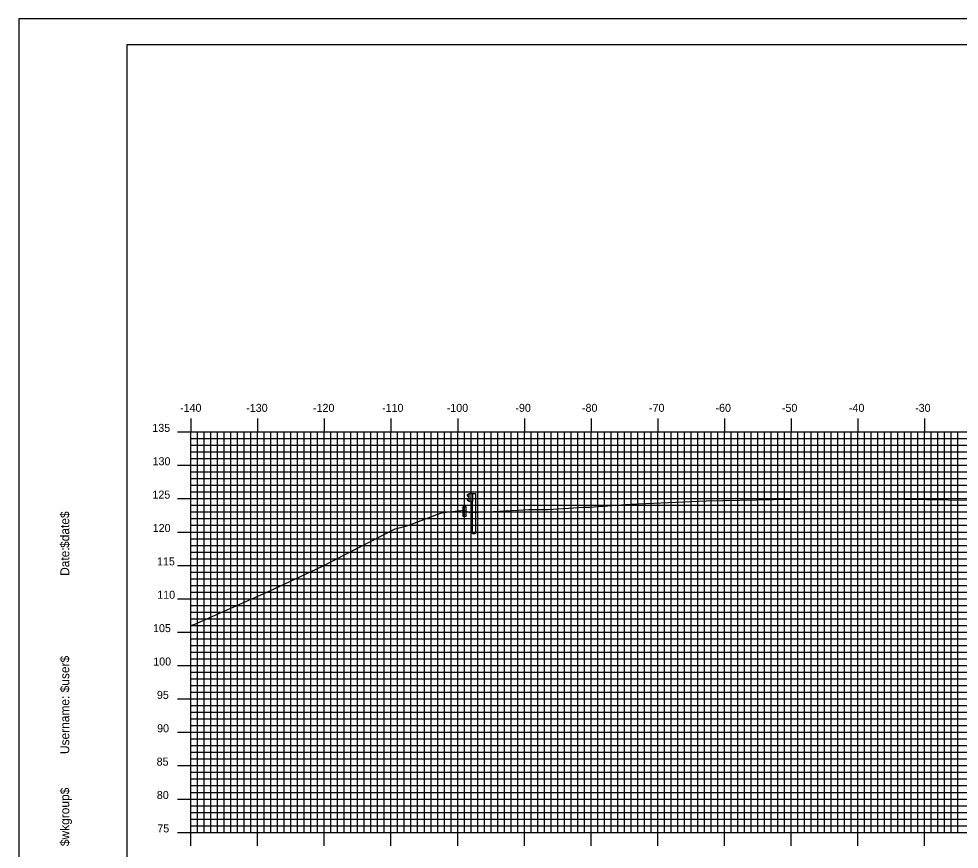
# Model space of a CAD drawing. Extents: x 857265 to 857608, y 364366 to 364586.
# Drawn here: x 857264.5 to 857405.5, y 364461.3 to 364585.7 of the extents above; entities that cross this region are included whole.
import ezdxf

# ---------------------------------------------------------------- set-up
doc = ezdxf.new("R2010")
doc.units = 0
for name, color, linetype in [('BORDER', 7, 'Continuous'), ('H_V ANNOTATION', 7, 'Continuous'), ('M_Roadway_Centerline', 7, 'Continuous'), ('MAJOR', 7, 'Continuous'), ('MINOR', 7, 'Continuous'), ('PLOT BOUNDARY', 7, 'Continuous'), ('S_Curb_Type_1', 7, 'Continuous'), ('S_Guardrail_Beam', 7, 'Continuous'), ('S_Roadway_Centerline', 7, 'Continuous')]:
    doc.layers.add(name, color=color, linetype=linetype)

msp = doc.modelspace()

# ---------------------------------------------------------------- linework, layer by layer
at = {"layer": 'BORDER'}
msp.add_lwpolyline([(857280.74, 364371.79), (857600.74, 364371.79), (857600.74, 364581.79), (857280.74, 364581.79)], close=True, dxfattribs=at)
at = {"layer": 'MAJOR'}
for p, q in [((857290.34, 364525.79), (857290.34, 364523.79)), ((857300.34, 364525.79), (857300.34, 364523.79)), ((857310.34, 364525.79), (857310.34, 364523.79)), ((857320.34, 364525.79), (857320.34, 364523.79)), ((857330.34, 364525.79), (857330.34, 364523.79)), ((857340.34, 364525.79), (857340.34, 364523.79)), ((857350.34, 364525.79), (857350.34, 364523.79)), ((857360.34, 364525.79), (857360.34, 364523.79)), ((857370.34, 364525.79), (857370.34, 364523.79)), ((857380.34, 364525.79), (857380.34, 364523.79)), ((857390.34, 364525.79), (857390.34, 364523.79)), ((857400.34, 364525.79), (857400.34, 364523.79)), ((857288.33, 364523.79), (857290.34, 364523.79)), ((857290.34, 364523.79), (857570.34, 364523.79)), ((857290.34, 364463.79), (857290.34, 364523.79)), ((857290.34, 364463.79), (857290.34, 364523.79)), ((857290.34, 364523.79), (857570.34, 364523.79)), ((857300.34, 364463.79), (857300.34, 364523.79)), ((857310.34, 364463.79), (857310.34, 364523.79)), ((857320.34, 364463.79), (857320.34, 364523.79)), ((857330.34, 364463.79), (857330.34, 364523.79)), ((857340.34, 364463.79), (857340.34, 364523.79)), ((857350.34, 364463.79), (857350.34, 364523.79)), ((857360.34, 364463.79), (857360.34, 364523.79)), ((857370.34, 364463.79), (857370.34, 364523.79)), ((857380.34, 364463.79), (857380.34, 364523.79)), ((857390.34, 364463.79), (857390.34, 364523.79)), ((857400.34, 364463.79), (857400.34, 364523.79)), ((857288.33, 364518.79), (857290.34, 364518.79)), ((857290.34, 364518.79), (857570.34, 364518.79)), ((857288.33, 364513.79), (857290.34, 364513.79)), ((857290.34, 364513.79), (857570.34, 364513.79)), ((857288.33, 364508.79), (857290.34, 364508.79)), ((857290.34, 364508.79), (857570.34, 364508.79)), ((857288.33, 364503.79), (857290.34, 364503.79)), ((857290.34, 364503.79), (857570.34, 364503.79)), ((857288.33, 364498.79), (857290.34, 364498.79)), ((857290.34, 364498.79), (857570.34, 364498.79)), ((857288.33, 364493.79), (857290.34, 364493.79)), ((857290.34, 364493.79), (857570.34, 364493.79)), ((857288.33, 364488.79), (857290.34, 364488.79)), ((857290.34, 364488.79), (857570.34, 364488.79)), ((857288.33, 364483.79), (857290.34, 364483.79)), ((857290.34, 364483.79), (857570.34, 364483.79)), ((857288.33, 364478.79), (857290.34, 364478.79)), ((857290.34, 364478.79), (857570.34, 364478.79)), ((857288.33, 364473.79), (857290.34, 364473.79)), ((857290.34, 364473.79), (857570.34, 364473.79)), ((857288.33, 364468.79), (857290.34, 364468.79)), ((857290.34, 364468.79), (857570.34, 364468.79)), ((857288.33, 364463.79), (857290.34, 364463.79)), ((857290.34, 364463.79), (857570.34, 364463.79)), ((857290.34, 364463.79), (857570.34, 364463.79)), ((857290.34, 364461.78), (857290.34, 364463.79)), ((857300.34, 364461.78), (857300.34, 364463.79)), ((857310.34, 364461.78), (857310.34, 364463.79)), ((857320.34, 364461.78), (857320.34, 364463.79)), ((857330.34, 364461.78), (857330.34, 364463.79)), ((857340.34, 364461.78), (857340.34, 364463.79)), ((857350.34, 364461.78), (857350.34, 364463.79)), ((857360.34, 364461.78), (857360.34, 364463.79)), ((857370.34, 364461.78), (857370.34, 364463.79)), ((857380.34, 364461.78), (857380.34, 364463.79)), ((857390.34, 364461.78), (857390.34, 364463.79)), ((857400.34, 364461.78), (857400.34, 364463.79))]:
    msp.add_line(p, q, dxfattribs=at)
at = {"layer": 'MINOR'}
for p, q in [((857291.34, 364463.79), (857291.34, 364523.79)), ((857292.34, 364463.79), (857292.34, 364523.79)), ((857293.34, 364463.79), (857293.34, 364523.79)), ((857294.34, 364463.79), (857294.34, 364523.79)), ((857295.34, 364463.79), (857295.34, 364523.79)), ((857296.34, 364463.79), (857296.34, 364523.79)), ((857297.34, 364463.79), (857297.34, 364523.79)), ((857298.34, 364463.79), (857298.34, 364523.79)), ((857299.34, 364463.79), (857299.34, 364523.79)), ((857301.34, 364463.79), (857301.34, 364523.79)), ((857302.34, 364463.79), (857302.34, 364523.79)), ((857303.34, 364463.79), (857303.34, 364523.79)), ((857304.34, 364463.79), (857304.34, 364523.79)), ((857305.34, 364463.79), (857305.34, 364523.79)), ((857306.34, 364463.79), (857306.34, 364523.79)), ((857307.34, 364463.79), (857307.34, 364523.79)), ((857308.34, 364463.79), (857308.34, 364523.79)), ((857309.34, 364463.79), (857309.34, 364523.79)), ((857311.34, 364463.79), (857311.34, 364523.79)), ((857312.34, 364463.79), (857312.34, 364523.79)), ((857313.34, 364463.79), (857313.34, 364523.79)), ((857314.34, 364463.79), (857314.34, 364523.79)), ((857315.34, 364463.79), (857315.34, 364523.79)), ((857316.34, 364463.79), (857316.34, 364523.79)), ((857317.34, 364463.79), (857317.34, 364523.79)), ((857318.34, 364463.79), (857318.34, 364523.79)), ((857319.34, 364463.79), (857319.34, 364523.79)), ((857321.34, 364463.79), (857321.34, 364523.79)), ((857322.34, 364463.79), (857322.34, 364523.79)), ((857323.34, 364463.79), (857323.34, 364523.79)), ((857324.34, 364463.79), (857324.34, 364523.79)), ((857325.34, 364463.79), (857325.34, 364523.79)), ((857326.34, 364463.79), (857326.34, 364523.79)), ((857327.34, 364463.79), (857327.34, 364523.79)), ((857328.34, 364463.79), (857328.34, 364523.79)), ((857329.34, 364463.79), (857329.34, 364523.79)), ((857331.34, 364463.79), (857331.34, 364523.79)), ((857332.34, 364463.79), (857332.34, 364523.79)), ((857333.34, 364463.79), (857333.34, 364523.79)), ((857334.34, 364463.79), (857334.34, 364523.79)), ((857335.34, 364463.79), (857335.34, 364523.79)), ((857336.34, 364463.79), (857336.34, 364523.79)), ((857337.34, 364463.79), (857337.34, 364523.79)), ((857338.34, 364463.79), (857338.34, 364523.79)), ((857339.34, 364463.79), (857339.34, 364523.79)), ((857341.34, 364463.79), (857341.34, 364523.79)), ((857342.34, 364463.79), (857342.34, 364523.79)), ((857343.34, 364463.79), (857343.34, 364523.79)), ((857344.34, 364463.79), (857344.34, 364523.79)), ((857345.34, 364463.79), (857345.34, 364523.79)), ((857346.34, 364463.79), (857346.34, 364523.79)), ((857347.34, 364463.79), (857347.34, 364523.79)), ((857348.34, 364463.79), (857348.34, 364523.79)), ((857349.34, 364463.79), (857349.34, 364523.79)), ((857351.34, 364463.79), (857351.34, 364523.79)), ((857352.34, 364463.79), (857352.34, 364523.79)), ((857353.34, 364463.79), (857353.34, 364523.79)), ((857354.34, 364463.79), (857354.34, 364523.79)), ((857355.34, 364463.79), (857355.34, 364523.79)), ((857356.34, 364463.79), (857356.34, 364523.79)), ((857357.34, 364463.79), (857357.34, 364523.79)), ((857358.34, 364463.79), (857358.34, 364523.79)), ((857359.34, 364463.79), (857359.34, 364523.79)), ((857361.34, 364463.79), (857361.34, 364523.79)), ((857362.34, 364463.79), (857362.34, 364523.79)), ((857363.34, 364463.79), (857363.34, 364523.79)), ((857364.34, 364463.79), (857364.34, 364523.79)), ((857365.34, 364463.79), (857365.34, 364523.79)), ((857366.34, 364463.79), (857366.34, 364523.79)), ((857367.34, 364463.79), (857367.34, 364523.79)), ((857368.34, 364463.79), (857368.34, 364523.79)), ((857369.34, 364463.79), (857369.34, 364523.79)), ((857371.34, 364463.79), (857371.34, 364523.79)), ((857372.34, 364463.79), (857372.34, 364523.79)), ((857373.34, 364463.79), (857373.34, 364523.79)), ((857374.34, 364463.79), (857374.34, 364523.79)), ((857375.34, 364463.79), (857375.34, 364523.79)), ((857376.34, 364463.79), (857376.34, 364523.79)), ((857377.34, 364463.79), (857377.34, 364523.79)), ((857378.34, 364463.79), (857378.34, 364523.79)), ((857379.34, 364463.79), (857379.34, 364523.79)), ((857381.34, 364463.79), (857381.34, 364523.79)), ((857382.34, 364463.79), (857382.34, 364523.79)), ((857383.34, 364463.79), (857383.34, 364523.79)), ((857384.34, 364463.79), (857384.34, 364523.79)), ((857385.34, 364463.79), (857385.34, 364523.79)), ((857386.34, 364463.79), (857386.34, 364523.79)), ((857387.34, 364463.79), (857387.34, 364523.79)), ((857388.34, 364463.79), (857388.34, 364523.79)), ((857389.34, 364463.79), (857389.34, 364523.79)), ((857391.34, 364463.79), (857391.34, 364523.79)), ((857392.34, 364463.79), (857392.34, 364523.79)), ((857393.34, 364463.79), (857393.34, 364523.79)), ((857394.34, 364463.79), (857394.34, 364523.79)), ((857395.34, 364463.79), (857395.34, 364523.79)), ((857396.34, 364463.79), (857396.34, 364523.79)), ((857397.34, 364463.79), (857397.34, 364523.79)), ((857398.34, 364463.79), (857398.34, 364523.79)), ((857399.34, 364463.79), (857399.34, 364523.79)), ((857401.34, 364463.79), (857401.34, 364523.79)), ((857402.34, 364463.79), (857402.34, 364523.79)), ((857403.34, 364463.79), (857403.34, 364523.79)), ((857404.34, 364463.79), (857404.34, 364523.79)), ((857405.34, 364463.79), (857405.34, 364523.79)), ((857290.34, 364522.79), (857570.34, 364522.79)), ((857290.34, 364522.79), (857292.34, 364522.79)), ((857290.34, 364521.79), (857570.34, 364521.79)), ((857290.34, 364521.79), (857292.34, 364521.79)), ((857290.34, 364520.79), (857570.34, 364520.79)), ((857290.34, 364520.79), (857292.34, 364520.79)), ((857290.34, 364519.79), (857570.34, 364519.79)), ((857290.34, 364519.79), (857292.34, 364519.79)), ((857290.34, 364517.79), (857570.34, 364517.79)), ((857290.34, 364517.79), (857292.34, 364517.79)), ((857290.34, 364516.79), (857570.34, 364516.79)), ((857290.34, 364516.79), (857292.34, 364516.79)), ((857290.34, 364515.79), (857570.34, 364515.79)), ((857290.34, 364515.79), (857292.34, 364515.79)), ((857290.34, 364514.79), (857570.34, 364514.79)), ((857290.34, 364514.79), (857292.34, 364514.79)), ((857290.34, 364512.79), (857570.34, 364512.79)), ((857290.34, 364512.79), (857292.34, 364512.79)), ((857290.34, 364511.79), (857570.34, 364511.79)), ((857290.34, 364511.79), (857292.34, 364511.79)), ((857290.34, 364510.79), (857570.34, 364510.79)), ((857290.34, 364510.79), (857292.34, 364510.79)), ((857290.34, 364509.79), (857570.34, 364509.79)), ((857290.34, 364509.79), (857292.34, 364509.79)), ((857290.34, 364507.79), (857570.34, 364507.79)), ((857290.34, 364507.79), (857292.34, 364507.79)), ((857290.34, 364506.79), (857570.34, 364506.79)), ((857290.34, 364506.79), (857292.34, 364506.79)), ((857290.34, 364505.79), (857570.34, 364505.79)), ((857290.34, 364505.79), (857292.34, 364505.79)), ((857290.34, 364504.79), (857570.34, 364504.79)), ((857290.34, 364504.79), (857292.34, 364504.79)), ((857290.34, 364502.79), (857570.34, 364502.79)), ((857290.34, 364502.79), (857292.34, 364502.79)), ((857290.34, 364501.79), (857570.34, 364501.79)), ((857290.34, 364501.79), (857292.34, 364501.79)), ((857290.34, 364500.79), (857570.34, 364500.79)), ((857290.34, 364500.79), (857292.34, 364500.79)), ((857290.34, 364499.79), (857570.34, 364499.79)), ((857290.34, 364499.79), (857292.34, 364499.79)), ((857290.34, 364497.79), (857570.34, 364497.79)), ((857290.34, 364497.79), (857292.34, 364497.79)), ((857290.34, 364496.79), (857570.34, 364496.79)), ((857290.34, 364496.79), (857292.34, 364496.79)), ((857290.34, 364495.79), (857570.34, 364495.79)), ((857290.34, 364495.79), (857292.34, 364495.79)), ((857290.34, 364494.79), (857570.34, 364494.79)), ((857290.34, 364494.79), (857292.34, 364494.79)), ((857290.34, 364492.79), (857570.34, 364492.79)), ((857290.34, 364492.79), (857292.34, 364492.79)), ((857290.34, 364491.79), (857570.34, 364491.79)), ((857290.34, 364491.79), (857292.34, 364491.79)), ((857290.34, 364490.79), (857570.34, 364490.79)), ((857290.34, 364490.79), (857292.34, 364490.79)), ((857290.34, 364489.79), (857570.34, 364489.79)), ((857290.34, 364489.79), (857292.34, 364489.79)), ((857290.34, 364487.79), (857570.34, 364487.79)), ((857290.34, 364487.79), (857292.34, 364487.79)), ((857290.34, 364486.79), (857570.34, 364486.79)), ((857290.34, 364486.79), (857292.34, 364486.79)), ((857290.34, 364485.79), (857570.34, 364485.79)), ((857290.34, 364485.79), (857292.34, 364485.79)), ((857290.34, 364484.79), (857570.34, 364484.79)), ((857290.34, 364484.79), (857292.34, 364484.79)), ((857290.34, 364482.79), (857570.34, 364482.79)), ((857290.34, 364482.79), (857292.34, 364482.79)), ((857290.34, 364481.79), (857570.34, 364481.79)), ((857290.34, 364481.79), (857292.34, 364481.79)), ((857290.34, 364480.79), (857570.34, 364480.79)), ((857290.34, 364480.79), (857292.34, 364480.79)), ((857290.34, 364479.79), (857570.34, 364479.79)), ((857290.34, 364479.79), (857292.34, 364479.79)), ((857290.34, 364477.79), (857570.34, 364477.79)), ((857290.34, 364477.79), (857292.34, 364477.79)), ((857290.34, 364476.79), (857570.34, 364476.79)), ((857290.34, 364476.79), (857292.34, 364476.79)), ((857290.34, 364475.79), (857570.34, 364475.79)), ((857290.34, 364475.79), (857292.34, 364475.79)), ((857290.34, 364474.79), (857570.34, 364474.79)), ((857290.34, 364474.79), (857292.34, 364474.79)), ((857290.34, 364472.79), (857570.34, 364472.79)), ((857290.34, 364472.79), (857292.34, 364472.79)), ((857290.34, 364471.79), (857570.34, 364471.79)), ((857290.34, 364471.79), (857292.34, 364471.79)), ((857290.34, 364470.79), (857570.34, 364470.79)), ((857290.34, 364470.79), (857292.34, 364470.79)), ((857290.34, 364469.79), (857570.34, 364469.79)), ((857290.34, 364469.79), (857292.34, 364469.79)), ((857290.34, 364467.79), (857570.34, 364467.79)), ((857290.34, 364467.79), (857292.34, 364467.79)), ((857290.34, 364466.79), (857570.34, 364466.79)), ((857290.34, 364466.79), (857292.34, 364466.79)), ((857290.34, 364465.79), (857570.34, 364465.79)), ((857290.34, 364465.79), (857292.34, 364465.79)), ((857290.34, 364464.79), (857570.34, 364464.79)), ((857290.34, 364464.79), (857292.34, 364464.79))]:
    msp.add_line(p, q, dxfattribs=at)
at = {"layer": 'PLOT BOUNDARY'}
msp.add_lwpolyline([(857264.55, 364365.67), (857604.55, 364365.67), (857604.55, 364585.67), (857264.55, 364585.67)], close=True, dxfattribs=at)
at = {"layer": 'S_Curb_Type_1'}
msp.add_lwpolyline([(857331.15, 364512.63), (857331.56, 364512.63), (857331.56, 364511.13), (857331.15, 364511.13)], close=True, dxfattribs=at)
msp.add_lwpolyline([(857331.15, 364512.63), (857331.56, 364512.63), (857331.56, 364511.13), (857331.15, 364511.13)], close=True, dxfattribs=at)
at = {"layer": 'S_Guardrail_Beam'}
for p, q in [((857331.95, 364514.46), (857331.81, 364514.36)), ((857331.95, 364514.46), (857331.81, 364514.36)), ((857331.81, 364514.21), (857332, 364514.08)), ((857331.81, 364514.21), (857332, 364514.08)), ((857332, 364513.86), (857331.81, 364513.72)), ((857332, 364513.86), (857331.81, 364513.72)), ((857332.05, 364514.48), (857331.97, 364514.46)), ((857332.05, 364514.48), (857331.97, 364514.46)), ((857332.03, 364514.01), (857332.03, 364513.92)), ((857332.03, 364514.01), (857332.03, 364513.92)), ((857332.05, 364514.55), (857332.54, 364514.55)), ((857332.05, 364513.38), (857332.05, 364514.55)), ((857332.05, 364514.55), (857332.54, 364514.55)), ((857332.05, 364513.38), (857332.05, 364514.55)), ((857332.54, 364514.55), (857333.03, 364514.55)), ((857332.54, 364514.55), (857332.54, 364513.38)), ((857332.54, 364514.55), (857333.03, 364514.55)), ((857332.54, 364514.55), (857332.54, 364513.38)), ((857333.03, 364514.55), (857333.03, 364508.55)), ((857333.03, 364514.55), (857333.03, 364508.55)), ((857331.81, 364513.58), (857331.95, 364513.48)), ((857331.81, 364513.58), (857331.95, 364513.48)), ((857331.97, 364513.47), (857332.05, 364513.46)), ((857331.97, 364513.47), (857332.05, 364513.46)), ((857332.54, 364513.38), (857332.05, 364513.38)), ((857332.54, 364513.38), (857332.05, 364513.38)), ((857332.54, 364508.55), (857332.54, 364513.38)), ((857332.54, 364508.55), (857332.54, 364513.38)), ((857332.54, 364508.55), (857333.03, 364508.55)), ((857332.54, 364508.55), (857333.03, 364508.55))]:
    msp.add_line(p, q, dxfattribs=at)
for centre, major_axis, start_param, end_param in [((857331.86, 364514.29), (-0.0877, 0), 5.323254, 7.243116), ((857331.86, 364514.29), (-0.0877, 0), 5.323254, 7.243116), ((857331.86, 364513.65), (-0.0877, 0), 5.323254, 7.243116), ((857331.86, 364513.65), (-0.0877, 0), 5.323254, 7.243116), ((857331.97, 364514.42), (-0.0417, 0), 4.886922, 5.323254), ((857331.97, 364514.42), (-0.0417, 0), 4.886922, 5.323254), ((857331.96, 364514.01), (0.0789, 0), 0, 0.959931), ((857331.96, 364514.01), (0.0789, 0), 0, 0.959931), ((857331.96, 364513.92), (0.0789, 0), 5.323254, 6.283185), ((857331.96, 364513.92), (0.0789, 0), 5.323254, 6.283185), ((857331.97, 364513.51), (-0.0417, 0), 0.959931, 1.396263), ((857331.97, 364513.51), (-0.0417, 0), 0.959931, 1.396263)]:
    msp.add_ellipse(centre, major_axis=major_axis, ratio=0.995501, start_param=start_param, end_param=end_param, dxfattribs=at)
at = {"layer": 'S_Roadway_Centerline'}
msp.add_lwpolyline([(857290.34, 364494.78), (857290.92, 364494.98), (857302.1, 364499.93), (857309.96, 364503.63), (857320.99, 364509.26), (857322.93, 364509.76), (857327.22, 364511.4), (857327.81, 364511.61), (857328.24, 364511.72), (857330.82, 364511.99), (857331.15, 364512.05), (857331.25, 364512), (857332.17, 364511.73), (857334.82, 364511.79), (857340.15, 364512.09), (857341.03, 364512.16), (857343.04, 364512.14), (857343.92, 364512.16), (857349.18, 364512.53), (857350.11, 364512.53), (857356.24, 364512.97), (857356.25, 364512.97), (857356.29, 364512.97), (857356.3, 364512.97), (857356.32, 364512.97), (857367.61, 364513.44), (857380.16, 364513.73), (857381.5, 364513.77), (857382.5, 364513.79), (857386.91, 364513.87), (857390.59, 364513.83), (857394.05, 364513.77), (857407.18, 364513.58)], dxfattribs=at)

# ---------------------------------------------------------------- texts
at = {"layer": 'BORDER'}
for s, p in [('$date$', (857272.11, 364506.4)), ('Date:', (857272.11, 364502.22)), ('$user$', (857272.11, 364484.77)), ('Username:', (857272.11, 364475.52)), ('$wkgroup$', (857272.11, 364461.73))]:
    msp.add_text(s, height=1.339, rotation=90, dxfattribs=at).set_placement(p)
at = {"layer": 'H_V ANNOTATION'}
for s, p in [('-140', (857288.72, 364526.79)), ('-130', (857298.64, 364526.79)), ('-120', (857308.65, 364526.79)), ('-110', (857319, 364526.79)), ('-100', (857328.7, 364526.79)), ('-90', (857338.99, 364526.79)), ('-80', (857348.97, 364526.79)), ('-70', (857359.02, 364526.79)), ('-60', (857368.99, 364526.79)), ('-50', (857378.94, 364526.79)), ('-40', (857388.99, 364526.79)), ('-30', (857398.91, 364526.79)), ('135', (857284.56, 364523.79)), ('130', (857284.6, 364518.79)), ('125', (857284.58, 364513.79)), ('120', (857284.62, 364508.79)), ('115', (857285.27, 364503.79)), ('110', (857285.3, 364498.79)), ('105', (857284.67, 364493.79)), ('100', (857284.7, 364488.79)), ('95', (857285.25, 364483.79)), ('90', (857285.28, 364478.79)), ('85', (857285.21, 364473.79)), ('80', (857285.24, 364468.79)), ('75', (857285.31, 364463.79))]:
    msp.add_text(s, height=1.2, dxfattribs=at).set_placement(p)
at = {"layer": 'M_Roadway_Centerline'}
for s, p in [('C', (857386.9, 364513.87)), ('L', (857386.91, 364513.86)), ('C', (857349.17, 364512.53)), ('L', (857349.18, 364512.52))]:
    msp.add_text(s, height=0.0146, dxfattribs=at).set_placement(p)
at = {"layer": 'MAJOR'}
msp.add_text('-', height=0.012, dxfattribs=at).set_placement((857290.33, 364463.79))

doc.saveas('drawing.dxf')
